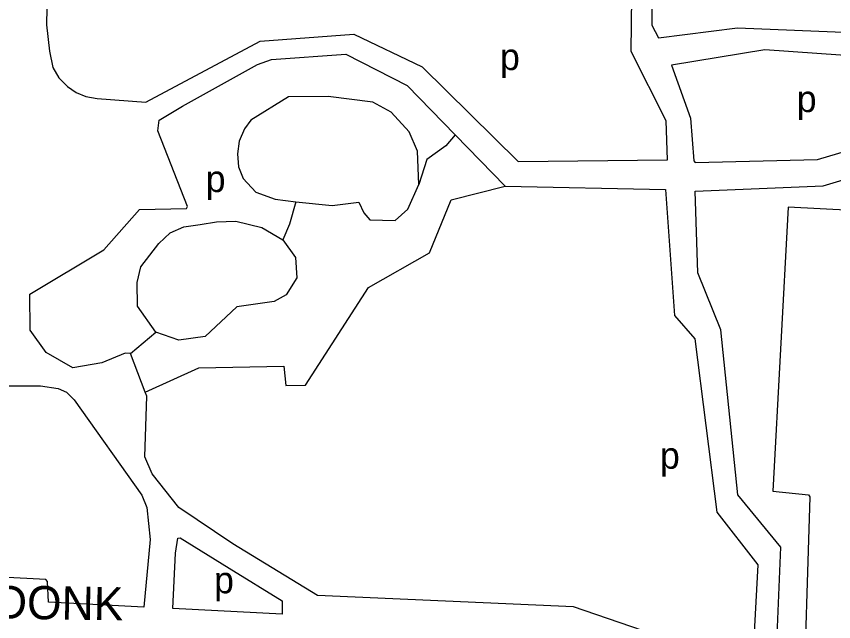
# Model space of a CAD drawing. Extents: x 163026 to 166241, y 382475 to 384501.
# Drawn here: x 164462 to 164584.9, y 383904.4 to 383995.6 of the extents above; entities that cross this region are included whole.
import ezdxf

# ---------------------------------------------------------------- set-up
doc = ezdxf.new("R2010")
doc.units = 0
for name, color, linetype in [('BLT_Basislijn', 7, 'Continuous'), ('BLT_Centroide', 7, 'Continuous'), ('BLT_Straatnaam', 7, 'Continuous')]:
    doc.layers.add(name, color=color, linetype=linetype)

msp = doc.modelspace()

# ---------------------------------------------------------------- linework, layer by layer
at = {"layer": 'BLT_Basislijn'}
for p, q in [((164520.75, 383985.15), (164527.98, 383977.74)), ((164527.98, 383977.74), (164526.6, 383976.08)), ((164526.6, 383976.08), (164523.71, 383974.02)), ((164523.71, 383974.02), (164522.52, 383970.23)), ((164504, 383967.62), (164503.06, 383964.25)), ((164503.06, 383964.25), (164502.07, 383961.91)), ((164479.15, 383944.79), (164482.96, 383947.99))]:
    msp.add_line(p, q, dxfattribs=at)
for points in [[(164557.59, 383999.74), (164557.57, 383994.23), (164558.56, 383992.32), (164570.47, 383993.86), (164610.91, 383992.2), (164643.66, 383994.77), (164656.95, 384001.87), (164662.56, 384003.09), (164663.35, 384004.36), (164662.59, 384014.31), (164652.96, 384015.07)], [(164470.09, 384013.19), (164463.3, 384010.39), (164463.34, 384009.72), (164466.71, 384004.56), (164466.48, 383994.31), (164466.93, 383990.34), (164467.42, 383987.85), (164468.35, 383986.33), (164469.66, 383984.98), (164470.93, 383984.12), (164472.41, 383983.5), (164474.13, 383983.21), (164481.45, 383982.64), (164498.65, 383991.84), (164512.73, 383992.88), (164523.03, 383987.94), (164537.46, 383973.71), (164559.91, 383973.98), (164559.75, 383979.81), (164554.48, 383990.27), (164554.57, 383998.62)], [(164582.4, 383989.97), (164574.59, 383990.52), (164560.51, 383988.23), (164563.39, 383980.24), (164563.87, 383973.83), (164564.09, 383973.58), (164582.48, 383974.02), (164594.33, 383977.53), (164604.3, 383986.65), (164604.3, 383987.06), (164603.02, 383988.53), (164582.4, 383989.97)], [(164487.56, 383966.65), (164487.71, 383966.92), (164483.25, 383978.33), (164483.45, 383979.93), (164486.95, 383982.02), (164498.25, 383988.3), (164500.34, 383989.09), (164511.55, 383989.85), (164520.75, 383985.15)], [(164508.89, 383983.5), (164502.88, 383983.43), (164497.21, 383979.92), (164496.26, 383978.65), (164495.46, 383976.78), (164495.22, 383974.87), (164495.4, 383972.93), (164496.1, 383971.14), (164498.01, 383969.09), (164500.88, 383968.02), (164504, 383967.62)], [(164522.52, 383970.23), (164522.33, 383975.24), (164521.05, 383978.19), (164518.34, 383981.13), (164515.6, 383982.63), (164508.89, 383983.5)], [(164527.98, 383977.74), (164535.52, 383970)], [(164582.29, 383868.85), (164577.21, 383869.04), (164575.13, 383871.08), (164576.98, 383915.64), (164570.51, 383923.51), (164567.96, 383948.37), (164564.49, 383956.94), (164564.09, 383969.26), (164583.36, 383970.04), (164598.4, 383974.57), (164606.16, 383969.43), (164611.03, 383968.95), (164610.75, 383965.24)], [(164504, 383967.62), (164509.48, 383967.1), (164513.5, 383967.61), (164514.26, 383965.97), (164515.14, 383964.91), (164518.96, 383964.83), (164520.86, 383966.54), (164522.52, 383970.23)], [(164535.52, 383970), (164559.63, 383969.49), (164560.98, 383950.52), (164564.04, 383947), (164567.37, 383920.9), (164573.54, 383912.99), (164572.43, 383892.56), (164571.98, 383892.52), (164556.17, 383903.07), (164545.81, 383906.67), (164507.25, 383908.37), (164494.55, 383916.12), (164486.38, 383921.6), (164482.39, 383926.7), (164481.28, 383929.25), (164481.56, 383938.35), (164481.34, 383939)], [(164481.34, 383939), (164489.4, 383942.63), (164502.18, 383942.88), (164502.48, 383939.96), (164505.47, 383940.04), (164514.96, 383954.74), (164524.14, 383959.94), (164527.39, 383967.94), (164535.52, 383970)], [(164481.34, 383939), (164479.15, 383944.79), (164478.33, 383944.83), (164474.81, 383943.39), (164470.44, 383942.63), (164466.46, 383944.93), (164464.02, 383948.29), (164463.97, 383953.72), (164475.12, 383960.42), (164480.48, 383966.47), (164487.56, 383966.65)], [(164587.71, 383966.34), (164578.1, 383966.85), (164575.8, 383924.07), (164581.13, 383923.51), (164581.36, 383923.22), (164580.27, 383889.28), (164582.96, 383888.9), (164582.29, 383868.85)], [(164482.96, 383947.99), (164480.16, 383951.94), (164480.14, 383955.5), (164480.7, 383957.87), (164483.38, 383961.36), (164485.1, 383962.97), (164487.17, 383963.88), (164489.62, 383964.24)], [(164489.62, 383964.24), (164492.06, 383964.61)], [(164492.06, 383964.61), (164494.98, 383964.71), (164498.87, 383963.78), (164502.07, 383961.91)], [(164502.07, 383961.91), (164503.97, 383959.27), (164504.17, 383956.18), (164502.57, 383953.63), (164500.72, 383952.61), (164495.14, 383951.81), (164490.36, 383947.35), (164486.38, 383946.78), (164482.96, 383947.99)], [(164418.48, 383908.88), (164418.62, 383909.75), (164420.6, 383913.42), (164422.27, 383919.02), (164422.36, 383931), (164423.75, 383933.2), (164424.71, 383934.03), (164430.28, 383934.72), (164441.12, 383930.11), (164443.57, 383930.16), (164445.22, 383931.07), (164457.06, 383939.92), (164465.56, 383939.92), (164468.25, 383939.55), (164469.48, 383938.97), (164470.66, 383937.84), (164480.82, 383923.46), (164481.6, 383921.6), (164482.11, 383916.79), (164481.12, 383906.62)], [(164493.97, 383912.48), (164501.93, 383907.54), (164501.97, 383905.54), (164485.5, 383906.42), (164485.9, 383914.71), (164486.26, 383916.98), (164486.58, 383917.06), (164493.97, 383912.48)], [(164481.12, 383906.62), (164466.77, 383907.37), (164466.63, 383910.49), (164466.37, 383910.76), (164440.39, 383912.11), (164437.77, 383912.2), (164437.52, 383911.81), (164437.23, 383907.89), (164418.48, 383908.88)]]:
    msp.add_lwpolyline(points, dxfattribs=at)

# ---------------------------------------------------------------- texts
at = {"layer": 'BLT_Centroide'}
for p in [(164534.73, 383987.48), (164579.38, 383981.15), (164490.45, 383969.11), (164558.8, 383927.45), (164491.71, 383908.69)]:
    msp.add_text('p', height=4, dxfattribs=at).set_placement(p)
at = {"layer": 'BLT_Straatnaam'}
msp.add_text('DONK', height=5, rotation=359.1402, dxfattribs=at).set_placement((164458.7, 383904.89))

doc.saveas('drawing.dxf')
